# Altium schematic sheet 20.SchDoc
size 337 x 236 mm
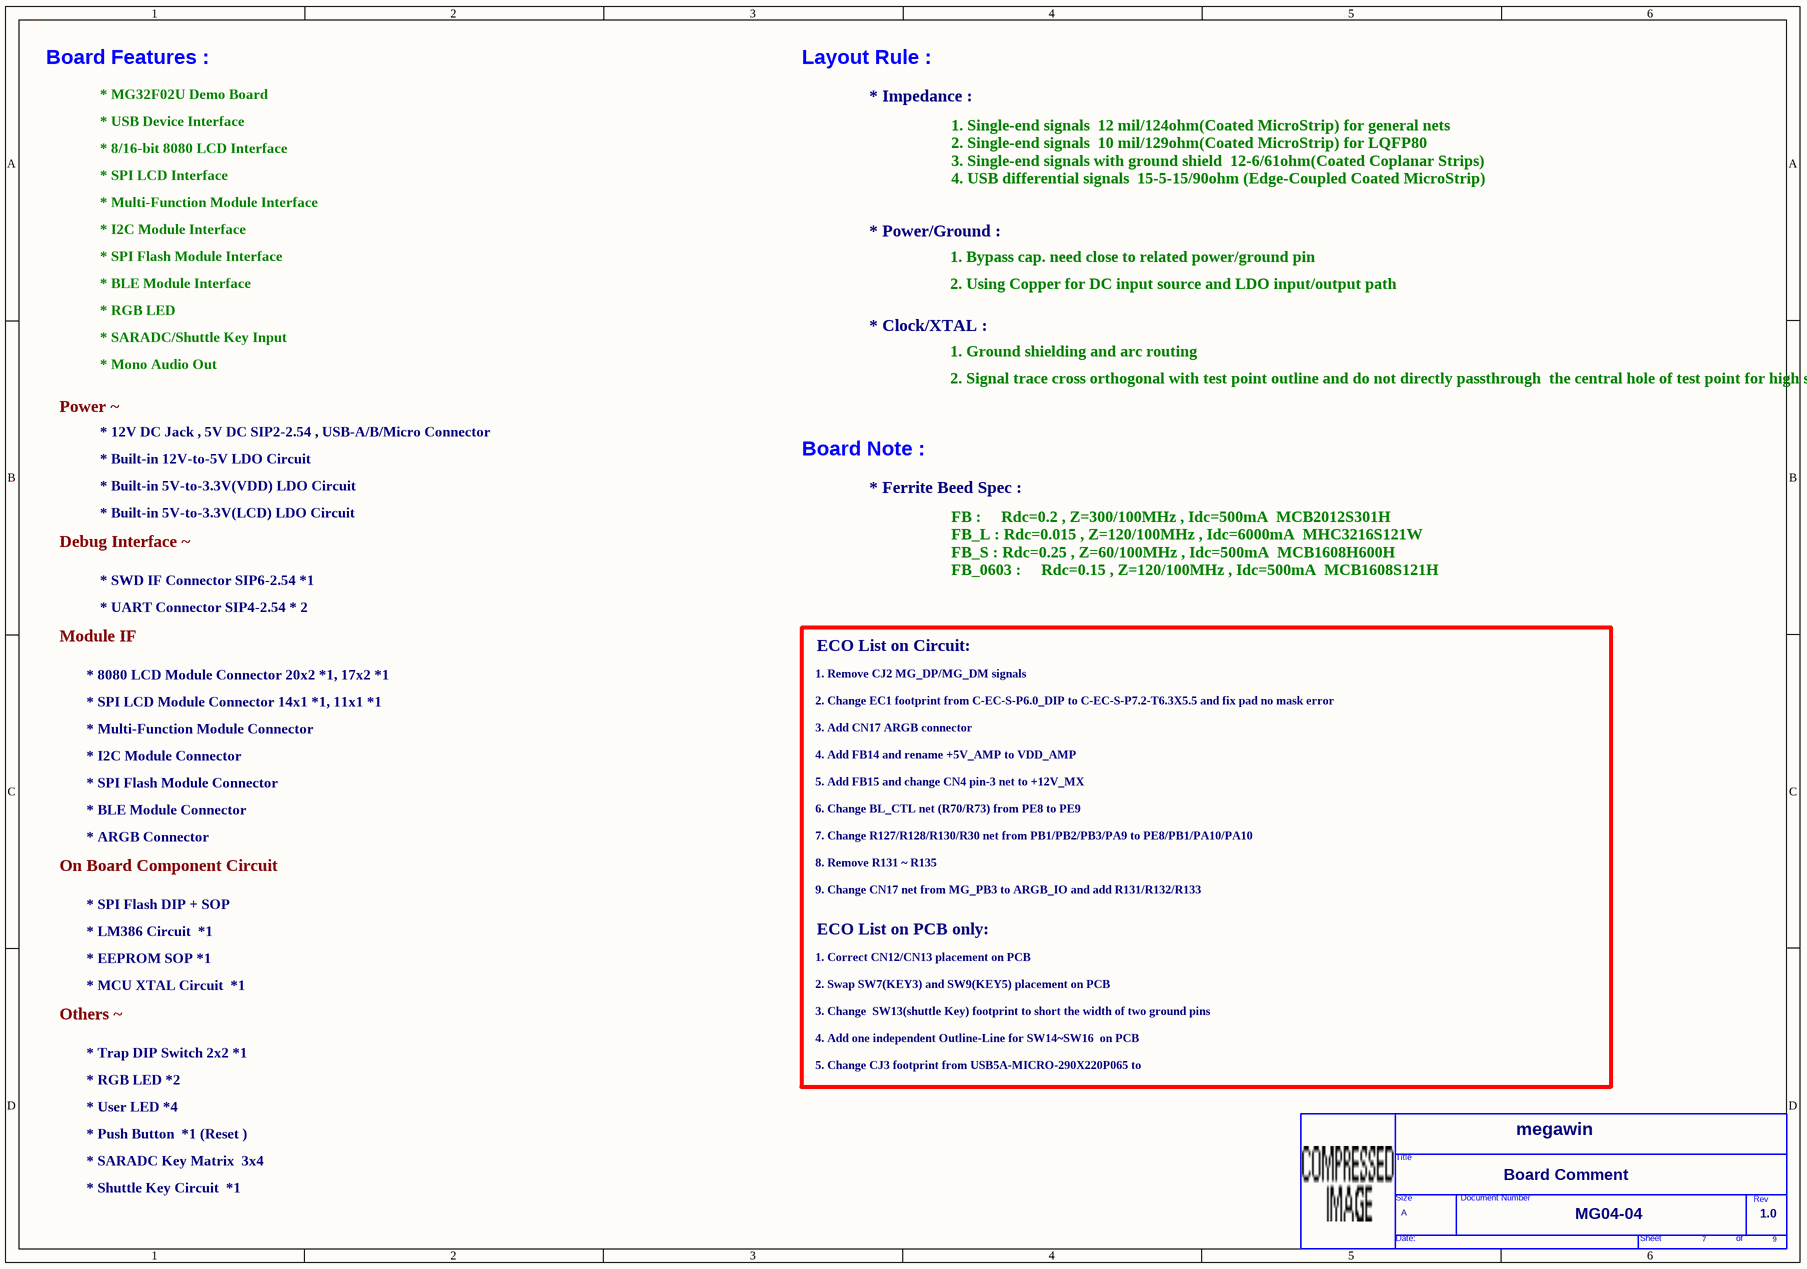
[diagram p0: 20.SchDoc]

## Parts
*  OrgName: megawin  Doc: MG04-04  RevCode: 1.0  Title: Board Comment  Page Size: A  Page Number: 7  Page Count: 9  (hidden comment: TitleBlock_MegaWin)  (graphical)

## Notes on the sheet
- Board Features :
- Layout Rule :
- * MG32F02U Demo Board
- * USB Device Interface
- * Impedance :
- * Multi-Function Module Interface
- * 8/16-bit 8080 LCD Interface
- * SPI LCD Interface
- * SPI Flash Module Interface
- * I2C Module Interface
- * Power/Ground :
- 1. Bypass cap. need close to related power/ground pin
- 1. Single-end signals  12 mil/124ohm(Coated MicroStrip) for general nets
  2. Single-end signals  10 mil/129ohm(Coated MicroStrip) for LQFP80
  3. Single-end signals with ground shield  12-6/61ohm(Coated Coplanar Strips)
  4. USB differential signals  15-5-15/90ohm (Edge-Coupled Coated MicroStrip)
- * RGB LED
- * SARADC/Shuttle Key Input
- * BLE Module Interface
- * Clock/XTAL :
- 2. Using Copper for DC input source and LDO input/output path
- Power ~
- * Mono Audio Out
- 1. Ground shielding and arc routing
- 2. Signal trace cross orthogonal with test point outline and do not directly passthrough  the central hole of test point for high speed signal
- * Built-in 12V-to-5V LDO Circuit
- * 12V DC Jack , 5V DC SIP2-2.54 , USB-A/B/Micro Connector
- Board Note :
- Debug Interface ~
- * Built-in 5V-to-3.3V(VDD) LDO Circuit
- * Built-in 5V-to-3.3V(LCD) LDO Circuit
- * Ferrite Beed Spec :
- * SWD IF Connector SIP6-2.54 *1
- * UART Connector SIP4-2.54 * 2
- FB :     Rdc=0.2 , Z=300/100MHz , Idc=500mA  MCB2012S301H
  FB_L : Rdc=0.015 , Z=120/100MHz , Idc=6000mA  MHC3216S121W
  FB_S : Rdc=0.25 , Z=60/100MHz , Idc=500mA  MCB1608H600H
  FB_0603 :     Rdc=0.15 , Z=120/100MHz , Idc=500mA  MCB1608S121H
- Module IF
- * 8080 LCD Module Connector 20x2 *1, 17x2 *1
- 1. Remove CJ2 MG_DP/MG_DM signals
- ECO List on Circuit:
- * Multi-Function Module Connector
- * SPI LCD Module Connector 14x1 *1, 11x1 *1
- 2. Change EC1 footprint from C-EC-S-P6.0_DIP to C-EC-S-P7.2-T6.3X5.5 and fix pad no mask error
- 3. Add CN17 ARGB connector
- * SPI Flash Module Connector
- * I2C Module Connector
- * BLE Module Connector
- 4. Add FB14 and rename +5V_AMP to VDD_AMP
- 5. Add FB15 and change CN4 pin-3 net to +12V_MX
- 6. Change BL_CTL net (R70/R73) from PE8 to PE9
- On Board Component Circuit
- * ARGB Connector
- 7. Change R127/R128/R130/R30 net from PB1/PB2/PB3/PA9 to PE8/PB1/PA10/PA10
- 8. Remove R131 ~ R135
- * LM386 Circuit  *1
- * SPI Flash DIP + SOP
- 9. Change CN17 net from MG_PB3 to ARGB_IO and add R131/R132/R133
- ECO List on PCB only:
- Others ~
- * MCU XTAL Circuit  *1
- * EEPROM SOP *1
- 1. Correct CN12/CN13 placement on PCB
- 2. Swap SW7(KEY3) and SW9(KEY5) placement on PCB
- 3. Change  SW13(shuttle Key) footprint to short the width of two ground pins
- * Trap DIP Switch 2x2 *1
- * RGB LED *2
- 4. Add one independent Outline-Line for SW14~SW16  on PCB
- 5. Change CJ3 footprint from USB5A-MICRO-290X220P065 to
- * Push Button  *1 (Reset )
- * User LED *4
- * SARADC Key Matrix  3x4
- * Shuttle Key Circuit  *1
